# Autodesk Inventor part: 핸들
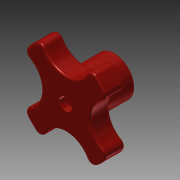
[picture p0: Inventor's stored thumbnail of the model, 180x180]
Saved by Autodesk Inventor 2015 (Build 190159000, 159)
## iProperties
Created: 2018-01
Part Number: 핸들
Material: ABS 플라스틱
Document SubType Name: Modeling
Designer: mduedu
Density: 1 g/cm^3
Appearance: 주황색-빨간색
Author: mduedu
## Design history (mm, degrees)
sketch "스케치1"
  geometry: C1 r 10 at (0, 0); C2 r 25 at (0, 0); 1 further point
  constraints: 2 centre point, 2 coincident
  dimensions: "d0" = 20 diameter of C1; "d1" = 50 diameter of C2
extrude "돌출1" new body sketch "스케치1" distance "d2" = 15; taper "d3" = 0 deg
extrude "돌출2" join sketch "스케치1" distance "d4" = 10; taper "d5" = 0 deg
sketch "스케치2" dims "d8" = 15
  geometry: L1 (-6, -6)-(-4.5, -6); L2 (6, -6)-(6, -4.5); L3 (6, 6)-(4.5, 6); L4 (-6, 6)-(-6, 4.5); L5 (-6, -6)-(6, 6); L6 (6, -6)-(-6, 6); L7 (-4.5, 6)-(-6, 6); L8 (4.5, 6)-(-4.5, 6); L9 (6, 4.5)-(6, 6); L10 (6, -4.5)-(6, 4.5); L11 (4.5, -6)-(6, -6); L12 (-4.5, -6)-(4.5, -6); L13 (-6, -4.5)-(-6, -6); L14 (-6, 4.5)-(-6, -4.5); 2 further points
  constraints: 28 end point, 18 parallel, 9 perpendicular, 3 horizontal, 2 midpoint, 1 coincident, 10 other
  dimensions: "d6" = 12 distance of L4.start L3.start; "d7" = 12 distance of L3.start L2.start
extrude "돌출3" cut sketch "스케치2" distance "d9" = 15; taper "d10" = 0 deg
sketch "스케치3"
  geometry: C1 r 12.5 at (25, 0); 2 further points
  constraints: 2 horizontal alignment, 1 centre point, 1 other
  dimensions: "d14" = 25 diameter of C1
extrude "돌출4" cut sketch "스케치3" stored distance "d15" = 15; taper "d16" = 0 deg
fillet "모깎기1" dims "d20" = 3
fillet "모깎기2" dims "d24" = 1
sketch "스케치4"
  geometry: 2 further points
  constraints: 1 coincident
sketch "스케치5"
  geometry: 2 further points
  constraints: 1 coincident
hole "구멍1" sketch "스케치5" at (0, 0) diameter "d25" = 3.4; stored, may be unused: countersink angle "d29" = 90 deg, drill point angle "d31" = 0 deg; dims "d26" = 6, "d27" = 6.5, "d28" = 3.4, "d30" = 8
node "솔리드1"
pattern_circular "원형 패턴1" dims angle "d18" = 360 deg
pattern_circular "원형 패턴2" dims angle "d22" = 360 deg
node "투영된 루프1"
